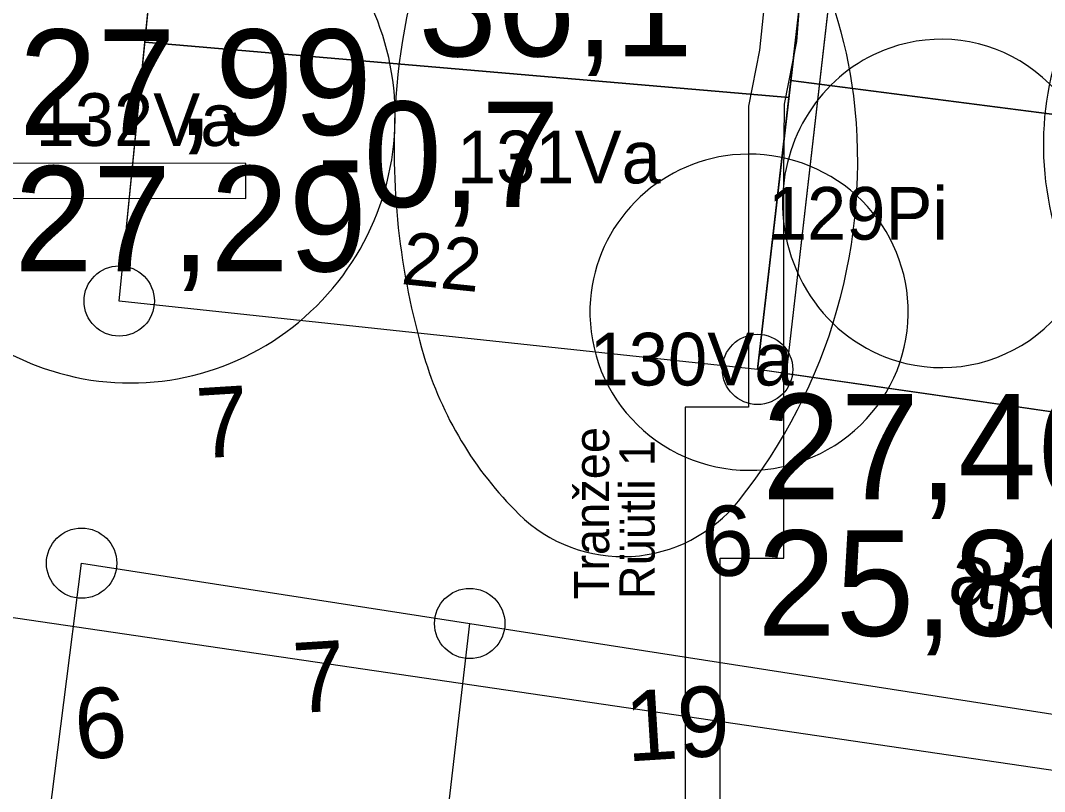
# Model space of a CAD drawing. Extents: x 738423 to 738903, y 6589762 to 6590172.
# Drawn here: x 738632.2 to 738661.32, y 6589853.54 to 6589875.49 of the extents above; entities that cross this region are included whole.
import ezdxf

# ---------------------------------------------------------------- set-up
doc = ezdxf.new("R2010")
doc.units = 0
for name, color, linetype in [('_1927_hoonestus', 7, 'Continuous'), ('_1927_katuse_kalded', 7, 'Continuous'), ('_1927_koordin_punktid_nr', 7, 'Continuous'), ('_1927_krundi_piir', 7, 'Continuous'), ('_a_ajalooline_maapind', 7, 'Continuous'), ('_a_olol_maapind', 7, 'Continuous'), ('_ajalooline_aadress', 7, 'Continuous'), ('_arheol_Raamatukogu_tekst', 7, 'Continuous'), ('_arheol_Raamatukogu_tranžee', 7, 'Continuous'), ('a_dendro_II_Vkl_puu', 7, 'Continuous'), ('a_dendro_III_vk_puu', 7, 'Continuous'), ('a_dendro_puu_nr', 7, 'Continuous'), ('Default', 7, 'Continuous'), ('plan_ala', 7, 'Continuous'), ('v_vormistus_tekst', 7, 'Continuous')]:
    doc.layers.add(name, color=color, linetype=linetype)

# ---------------------------------------------------------------- blocks, each defined once
blk = doc.blocks.new('_U577')
at = {"layer": 'Default'}
for centre, radius, start, end in [((0.0003539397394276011, -0.0024772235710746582), 0.01753301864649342, 95.06339460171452, 143.64928581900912), ((0.0003509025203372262, -0.0024429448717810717), 0.017498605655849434, 47.6139328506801, 95.06339460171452), ((0.006587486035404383, 0.004390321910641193), 0.008247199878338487, 335.85757945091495, 47.613932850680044), ((-0.007106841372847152, 0.0030134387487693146), 0.008269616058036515, 143.6492858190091, 217.25092224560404), ((0.00326511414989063, 0.0058794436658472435), 0.011888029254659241, 301.16151048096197, 335.85757945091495), ((-0.004085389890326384, 0.00531108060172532), 0.012065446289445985, 217.2509222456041, 249.96613917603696), ((-0.0012283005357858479, 0.013310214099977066), 0.02057175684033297, 274.9595126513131, 301.16151048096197), ((-0.0012168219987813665, 0.01317793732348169), 0.020438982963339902, 249.96613917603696, 274.9595126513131)]:
    blk.add_arc(centre, radius, start, end, dxfattribs=at)
blk = doc.blocks.new('_U579')
at = {"layer": 'Default'}
for centre, radius, start, end in [((-0.00040469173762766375, -0.0036338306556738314), 0.00964728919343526, 90.6698769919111, 129.9961164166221), ((-0.00040544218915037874, -0.003569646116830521), 0.009583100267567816, 57.797497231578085, 90.6698769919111), ((-8.07417360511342e-05, -0.003054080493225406), 0.008973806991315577, 23.79468007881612, 57.797497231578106), ((-0.0008287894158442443, -0.0031283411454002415), 0.00898745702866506, 129.99611641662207, 170.80227761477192), ((0.00012402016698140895, -0.00296379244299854), 0.008750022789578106, 330.06495980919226, 23.79468007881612), ((-0.0010439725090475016, -0.0030934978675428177), 0.008769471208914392, 170.80227761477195, 225.9110289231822), ((-0.000504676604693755, -0.002601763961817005), 0.009475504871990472, 278.59055247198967, 330.06495980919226), ((-0.0005131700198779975, -0.002545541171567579), 0.009532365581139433, 225.91102892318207, 278.59055247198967)]:
    blk.add_arc(centre, radius, start, end, dxfattribs=at)
blk = doc.blocks.new('_U580')
at = {"layer": 'Default'}
for centre, radius, start, end in [((-0.0007351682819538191, -0.0009464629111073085), 0.008953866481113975, 89.56829725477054, 137.0360449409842), ((-0.0007352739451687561, -0.0009604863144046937), 0.008967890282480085, 49.77799837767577, 89.56829725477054), ((-0.0008139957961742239, -0.0010535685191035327), 0.00908979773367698, 10.266606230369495, 49.77799837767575), ((-0.000638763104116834, -0.001036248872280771), 0.00908560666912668, 137.0360449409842, 184.13744200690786), ((-0.000823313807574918, -0.0010552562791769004), 0.0090992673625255, 325.0458822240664, 10.266606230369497), ((-0.0006323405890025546, -0.001035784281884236), 0.009092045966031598, 184.13744200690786, 231.62212623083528), ((-0.0007170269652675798, -0.0011295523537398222), 0.008969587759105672, 279.4811897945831, 325.0458822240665), ((-0.000715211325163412, -0.0011404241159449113), 0.00895856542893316, 231.62212623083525, 279.4811897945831)]:
    blk.add_arc(centre, radius, start, end, dxfattribs=at)
blk = doc.blocks.new('_U581')
at = {"layer": 'Default'}
for centre, radius, start, end in [((-0.0003533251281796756, -0.035605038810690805), 0.04161816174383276, 90.22599422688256, 110.7235512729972), ((-0.0003746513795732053, -0.03019827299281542), 0.0362113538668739, 73.7512051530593, 90.22599422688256), ((0.004875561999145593, -0.012184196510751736), 0.01744778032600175, 49.92756766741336, 73.75120515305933), ((-0.007667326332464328, -0.016273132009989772), 0.02094892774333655, 110.7235512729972, 139.77080809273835), ((0.010993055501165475, -0.004912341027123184), 0.007944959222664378, 325.34619088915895, 49.92756766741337), ((-0.017226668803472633, -0.008186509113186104), 0.00842796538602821, 139.77080809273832, 235.64822831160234), ((-0.003462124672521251, 0.005079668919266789), 0.025517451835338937, 281.2397286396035, 325.3461908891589), ((-0.004520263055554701, 0.010404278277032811), 0.030946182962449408, 235.64822831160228, 281.2397286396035)]:
    blk.add_arc(centre, radius, start, end, dxfattribs=at)
blk = doc.blocks.new('_U582')
at = {"layer": 'Default'}
for centre, radius, start, end in [((-0.0007850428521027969, -0.005273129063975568), 0.015274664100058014, 90.12335565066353, 129.24551704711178), ((-0.000785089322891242, -0.005251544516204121), 0.015253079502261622, 56.96948488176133, 90.12335565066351), ((-0.0006696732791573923, -0.005074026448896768), 0.015041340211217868, 23.57628563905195, 56.969484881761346), ((-0.0009275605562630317, -0.005098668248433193), 0.0150493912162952, 129.24551704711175, 168.67143080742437), ((-0.0005917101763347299, -0.0050400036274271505), 0.014956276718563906, 330.9480012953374, 23.57628563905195), ((-0.0010119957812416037, -0.005081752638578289), 0.014963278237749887, 168.6714308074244, 224.00059475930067), ((-0.0008142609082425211, -0.004916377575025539), 0.015210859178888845, 278.7954697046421, 330.9480012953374), ((-0.0008177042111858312, -0.0048941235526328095), 0.01523337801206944, 224.00059475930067, 278.7954697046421)]:
    blk.add_arc(centre, radius, start, end, dxfattribs=at)

msp = doc.modelspace()

# ---------------------------------------------------------------- linework, layer by layer
at = {"layer": '_1927_hoonestus'}
for points in [[(738648.5572709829, 6589901.456803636), (738657.987576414, 6589900.425538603), (738653.971798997, 6589865.440014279), (738653.1607330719, 6589865.55689891), (738656.7595760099, 6589896.804037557), (738648.2717006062, 6589897.771571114)], [(738635.0048101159, 6589867.503013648), (738636.4693724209, 6589882.233909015), (738648.3801174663, 6589881.2516396), (738648.6253999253, 6589884.225871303), (738652.4080567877, 6589883.913918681), (738652.1613927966, 6589880.922934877), (738654.9075674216, 6589880.723877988), (738653.1607330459, 6589865.556898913)], [(738686.9079452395, 6589860.693508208), (738690.3471033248, 6589876.437885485), (738655.8073303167, 6589881.431195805), (738653.971798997, 6589865.440014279)]]:
    msp.add_lwpolyline(points, close=True, dxfattribs=at)
at = {"layer": '_1927_katuse_kalded'}
for points in [[(738635.7370912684, 6589874.86846133), (738636.469372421, 6589882.233909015), (738654.9075674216, 6589880.723877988), (738654.051851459, 6589873.294080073)], [(738654.1081769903, 6589873.783129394), (738655.0056644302, 6589881.575610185), (738655.8073303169, 6589881.431195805), (738690.3471033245, 6589876.437885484), (738688.7887442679, 6589869.303757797)], [(738635.7370912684, 6589874.86846133), (738654.051851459, 6589873.294080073), (738653.160733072, 6589865.556898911), (738635.0048101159, 6589867.503013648)], [(738654.1081769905, 6589873.783129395), (738688.788744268, 6589869.303757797), (738686.9079452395, 6589860.693508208), (738677.0811269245, 6589862.109674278), (738672.4076793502, 6589866.177638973), (738666.0829986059, 6589863.694640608), (738653.1607330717, 6589865.55689891)]]:
    msp.add_lwpolyline(points, close=True, dxfattribs=at)
at = {"layer": '_1927_koordin_punktid_nr'}
for centre in [(738635.0048101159, 6589867.503013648), (738653.160733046, 6589865.556898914), (738633.9361268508, 6589860.04223513), (738644.9741249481, 6589858.324475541)]:
    msp.add_circle(centre, 0.9999999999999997, dxfattribs=at)
at = {"layer": '_1927_krundi_piir'}
msp.add_line((738656.7595760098, 6589896.804037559), (738653.160733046, 6589865.556898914), dxfattribs=at)
for points in [[(738699.2597677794, 6589917.23983417), (738686.9079452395, 6589860.693508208), (738653.160733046, 6589865.556898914), (738635.0048101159, 6589867.503013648), (738638.1290908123, 6589898.927727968), (738639.279366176, 6589910.5516114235)], [(738630.9080977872, 6589836.248230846), (738648.7192322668, 6589832.597410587), (738649.4072489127, 6589837.158949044), (738651.2337120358, 6589851.119340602), (738644.2638507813, 6589852.188515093), (738644.9741249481, 6589858.324475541)]]:
    msp.add_lwpolyline(points, dxfattribs=at)
msp.add_lwpolyline([(738633.9361268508, 6589860.04223513), (738644.9741249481, 6589858.324475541), (738684.978134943, 6589852.097053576), (738681.439240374, 6589832.970330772), (738673.9180075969, 6589806.512115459), (738663.8382523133, 6589773.993292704), (738643.3161389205, 6589777.57560507), (738622.7595626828, 6589780.584670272), (738626.6204084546, 6589806.9353357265), (738627.9771447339, 6589816.20750196), (738629.4457483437, 6589826.258119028), (738630.9080977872, 6589836.248230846)], close=True, dxfattribs=at)
at = {"layer": '_arheol_Raamatukogu_tranžee'}
msp.add_lwpolyline([(738654.380448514, 6589880.19889457), (738653.399682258, 6589880.189044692), (738653.399682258, 6589876.385332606), (738653.2151971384, 6589874.643537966), (738652.8999019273, 6589873.047297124), (738652.8999019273, 6589864.483676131), (738651.0999019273, 6589864.483676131), (738651.0999019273, 6589848.68367613), (738652.0999019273, 6589848.68367613), (738652.0999019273, 6589860.18367613), (738653.9088242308, 6589860.18367613), (738653.9088242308, 6589871.007189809), (738653.923828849, 6589873.109334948), (738654.2799277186, 6589874.894069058), (738654.3869752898, 6589876.385332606), (738654.380448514, 6589880.19889457)], dxfattribs=at)
msp.add_lwpolyline([(738614.9711197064, 6589871.427585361), (738614.9709122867, 6589870.427585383), (738638.6059103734, 6589870.41807533), (738638.6061177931, 6589871.418075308)], close=True, dxfattribs=at)
at = {"layer": 'plan_ala'}
msp.add_lwpolyline([(738772.2221966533, 6589837.873120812), (738583.11, 6589865.669999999), (738583.11, 6589865.669999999), (738577.13, 6589865.85), (738565.7035831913, 6589866.139410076), (738565.4500000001, 6589885.77), (738564.4932191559, 6589941.052825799), (738581.9, 6589941.1499999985), (738615.11, 6589942.169999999), (738650.0499999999, 6589943.319999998), (738691.2690631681, 6589944.800325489), (738696.0901513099, 6589944.851371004), (738713.89, 6589945.129999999), (738703.51, 6589987.789999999), (738752.8799999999, 6590000.39), (738783.1408503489, 6590007.463828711), (738767.5688789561, 6589951.87996157)], close=True, dxfattribs=at)

# ---------------------------------------------------------------- block references
at = {"layer": 'a_dendro_II_Vkl_puu', "xscale": 500.0000000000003, "yscale": 500.0000000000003, "rotation": 85.69234851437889}
for name, p in [('_U577', (738668.8083105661, 6589871.8624428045)), ('_U580', (738652.425310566, 6589867.585442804))]:
    msp.add_blockref(name, p, dxfattribs=at)
at = {"layer": 'a_dendro_III_vk_puu', "xscale": 500.0000000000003, "yscale": 500.0000000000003, "rotation": 85.69234851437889}
for name, p in [('_U581', (738645.893310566, 6589873.338442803)), ('_U582', (738632.829310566, 6589873.347442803)), ('_U579', (738656.897310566, 6589870.628442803))]:
    msp.add_blockref(name, p, dxfattribs=at)

# ---------------------------------------------------------------- texts
at = {"layer": '_1927_koordin_punktid_nr'}
for s, p in [('7', (738637.2615922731, 6589863.0185568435)), ('6', (738651.6125324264, 6589859.633595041)), ('7', (738640.0099473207, 6589855.768726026)), ('6', (738633.7905191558, 6589854.449669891)), ('19', (738649.4550763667, 6589854.3939627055))]:
    msp.add_text(s, height=1.9999999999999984, rotation=3.560863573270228, dxfattribs=at).set_placement(p)
at = {"layer": '_a_ajalooline_maapind'}
for s, p in [('36,1', (738643.5130339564, 6589874.467036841)), ('-0,7', (738640.618354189, 6589870.180484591)), ('27,29', (738632.0176509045, 6589868.345143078)), ('25,86', (738653.1542820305, 6589857.973600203))]:
    msp.add_text(s, height=3, dxfattribs=at).set_placement(p)
at = {"layer": '_a_olol_maapind'}
for s, p in [('27,99', (738632.1521957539, 6589872.231766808)), ('27,46', (738653.2888268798, 6589861.860223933))]:
    msp.add_text(s, height=3, dxfattribs=at).set_placement(p)
at = {"layer": '_ajalooline_aadress'}
msp.add_text('22', height=1.4999999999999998, rotation=354.00562670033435, dxfattribs=at).set_placement((738642.9963586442, 6589867.990671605))
at = {"layer": '_arheol_Raamatukogu_tekst'}
for s, p in [('Tranžee ', (738648.9396093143, 6589859.011834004)), ('Rüütli 1', (738650.2338166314, 6589859.011834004))]:
    msp.add_text(s, height=1, rotation=89.99999999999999, dxfattribs=at).set_placement(p)
at = {"layer": 'a_dendro_puu_nr'}
for s, p in [('132Va', (738632.6248281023, 6589871.917860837)), ('131Va', (738644.6081706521, 6589870.852118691)), ('129Pi', (738653.4502885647, 6589869.248651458)), ('130Va', (738648.3832604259, 6589865.099118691))]:
    msp.add_text(s, height=1.5, dxfattribs=at).set_placement(p)
at = {"layer": 'v_vormistus_tekst'}
msp.add_text('ajalooline Rüütli tänav', height=1.7999999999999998, rotation=352.22707759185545, dxfattribs=at).set_placement((738658.5210745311, 6589858.907780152))

doc.saveas('drawing.dxf')
